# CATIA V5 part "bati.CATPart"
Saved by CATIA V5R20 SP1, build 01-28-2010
Part number: bati
Bounding box of the stored display mesh (mm): x -20 to 20, y -20 to 20, z 0 to 84.616
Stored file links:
  E:\EDELI\gcausse\Edeli_2012_613_gcausse\bati.CATPart
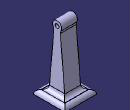
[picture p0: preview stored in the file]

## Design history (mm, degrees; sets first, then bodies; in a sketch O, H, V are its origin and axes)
Set1 "axe"
  Line1: type PtDir, RefPoint DatumPoint1, Direction DatumCurve1, Start 0, End 20
  DatumPoint1
  DatumCurve1
Body1 (main body)
  Sketch1 on xy-plane, origin (0, 0, 0), H (1, 0, 0), V (0, 1, 0)
    line L1 (-20, 20) -> (20, 20)
    line L2 (20, 20) -> (20, -20)
    line L3 (20, -20) -> (-20, -20)
    line L4 (-20, -20) -> (-20, 20)
    horizontal: L1 H, L3 H
    vertical: L2 V, L4 V
  Pad1: profile Sketch1, direction (0, 0, 1), length 5
  Sketch2 on end face of Pad1, origin (0, 0, 5), H (1, 0, 0), V (0, 1, 0)
    line L1 (-10, 10) -> (10, 10)
    line L2 (10, 10) -> (10, -10)
    line L3 (10, -10) -> (-10, -10)
    line L4 (-10, -10) -> (-10, 10)
    horizontal: L1 H, L3 H
    vertical: L2 V, L4 V
  Pad2: profile Sketch2, direction (0, 0, 1), length 80
  Sketch3 on face of Pad2 from Sketch2.L2, origin (10, 0, 0), H (0, 1, 0), V (0, 0, 1)
    line L1 (-10, 5) -> (-3.8991, 74.7336)
    point P1 (-10, 5)
    line L2 (10, 5) -> (3.8991, 74.7336)
    point P3 (10, 5)
    arc A1 centre (0, 79) radius 5.7797 from (3.8991, 74.7336) to (-3.8991, 74.7336) ccw
    point P5 (0, 79)
    point P6 (42, 90)
    reference projected point E1 (-10, 5) from vertex [face of Pad2 from Sketch2.L2 | end face of Pad1 | face of Pad2 from Sketch2.L3]
    reference projected point E2 (10, 5) from vertex [face of Pad2 from Sketch2.L2 | end face of Pad1 | face of Pad2 from Sketch2.L1]
    reference projected line E3 (-10, 5) -> (-10, 85) from edge [face of Pad2 from Sketch2.L2 | face of Pad2 from Sketch2.L3]
    reference projected line E4 (10, 5) -> (10, 85) from edge [face of Pad2 from Sketch2.L1 | face of Pad2 from Sketch2.L2]
    reference projected line E5 (-10, 85) -> (10, 85) from edge [face of Pad2 from Sketch2.L2 | end face of Pad2]
    line L3 (10, 5) -> (10, 100)
    line L4 (10, 100) -> (-10, 100)
    line L5 (-10, 100) -> (-10, 5)
    angle L1 E3 = 5
    angle L2 E4 = 5
    length L1 = 70
    length L2 = 70
    distance P5 E5 = 6
    coincidence: P1 E1, P3 E2
    vertical: L3 V, L5 V
    horizontal: L4 H
  Pocket1: profile Sketch3, direction (-1, 0, 0), length 80
  Fillet1: radius 5, on end face of Pad1
  Sketch4 on face of Pad2 from Sketch2.L2, origin (10, 2.3527, 80.577), H (0, 1, 0), V (0, 0, 1)
    point P1 (-2.3527, -1.577)
    reference projected arc E1 centre (-2.3527, -1.577) radius 5.7797 from (1.5464, -5.8433) to (-6.2518, -5.8433) ccw from edge [face of Pad2 from Sketch2.L2 | face of Pocket1 from Sketch3.A1]
    concentricity: P1 E1
  Hole1: placed by Sketch4, at (10, 0, 79) direction (-1, 0, 0), diameter 5, depth 20
  Fillet2: radius 5, on edge [face of Pocket1 from Sketch3.A1 | face of Pocket1 from Sketch3.L1]; edge [face of Pocket1 from Sketch3.L2 | face of Pocket1 from Sketch3.A1]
